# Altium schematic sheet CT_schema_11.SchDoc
size 387 x 278 mm
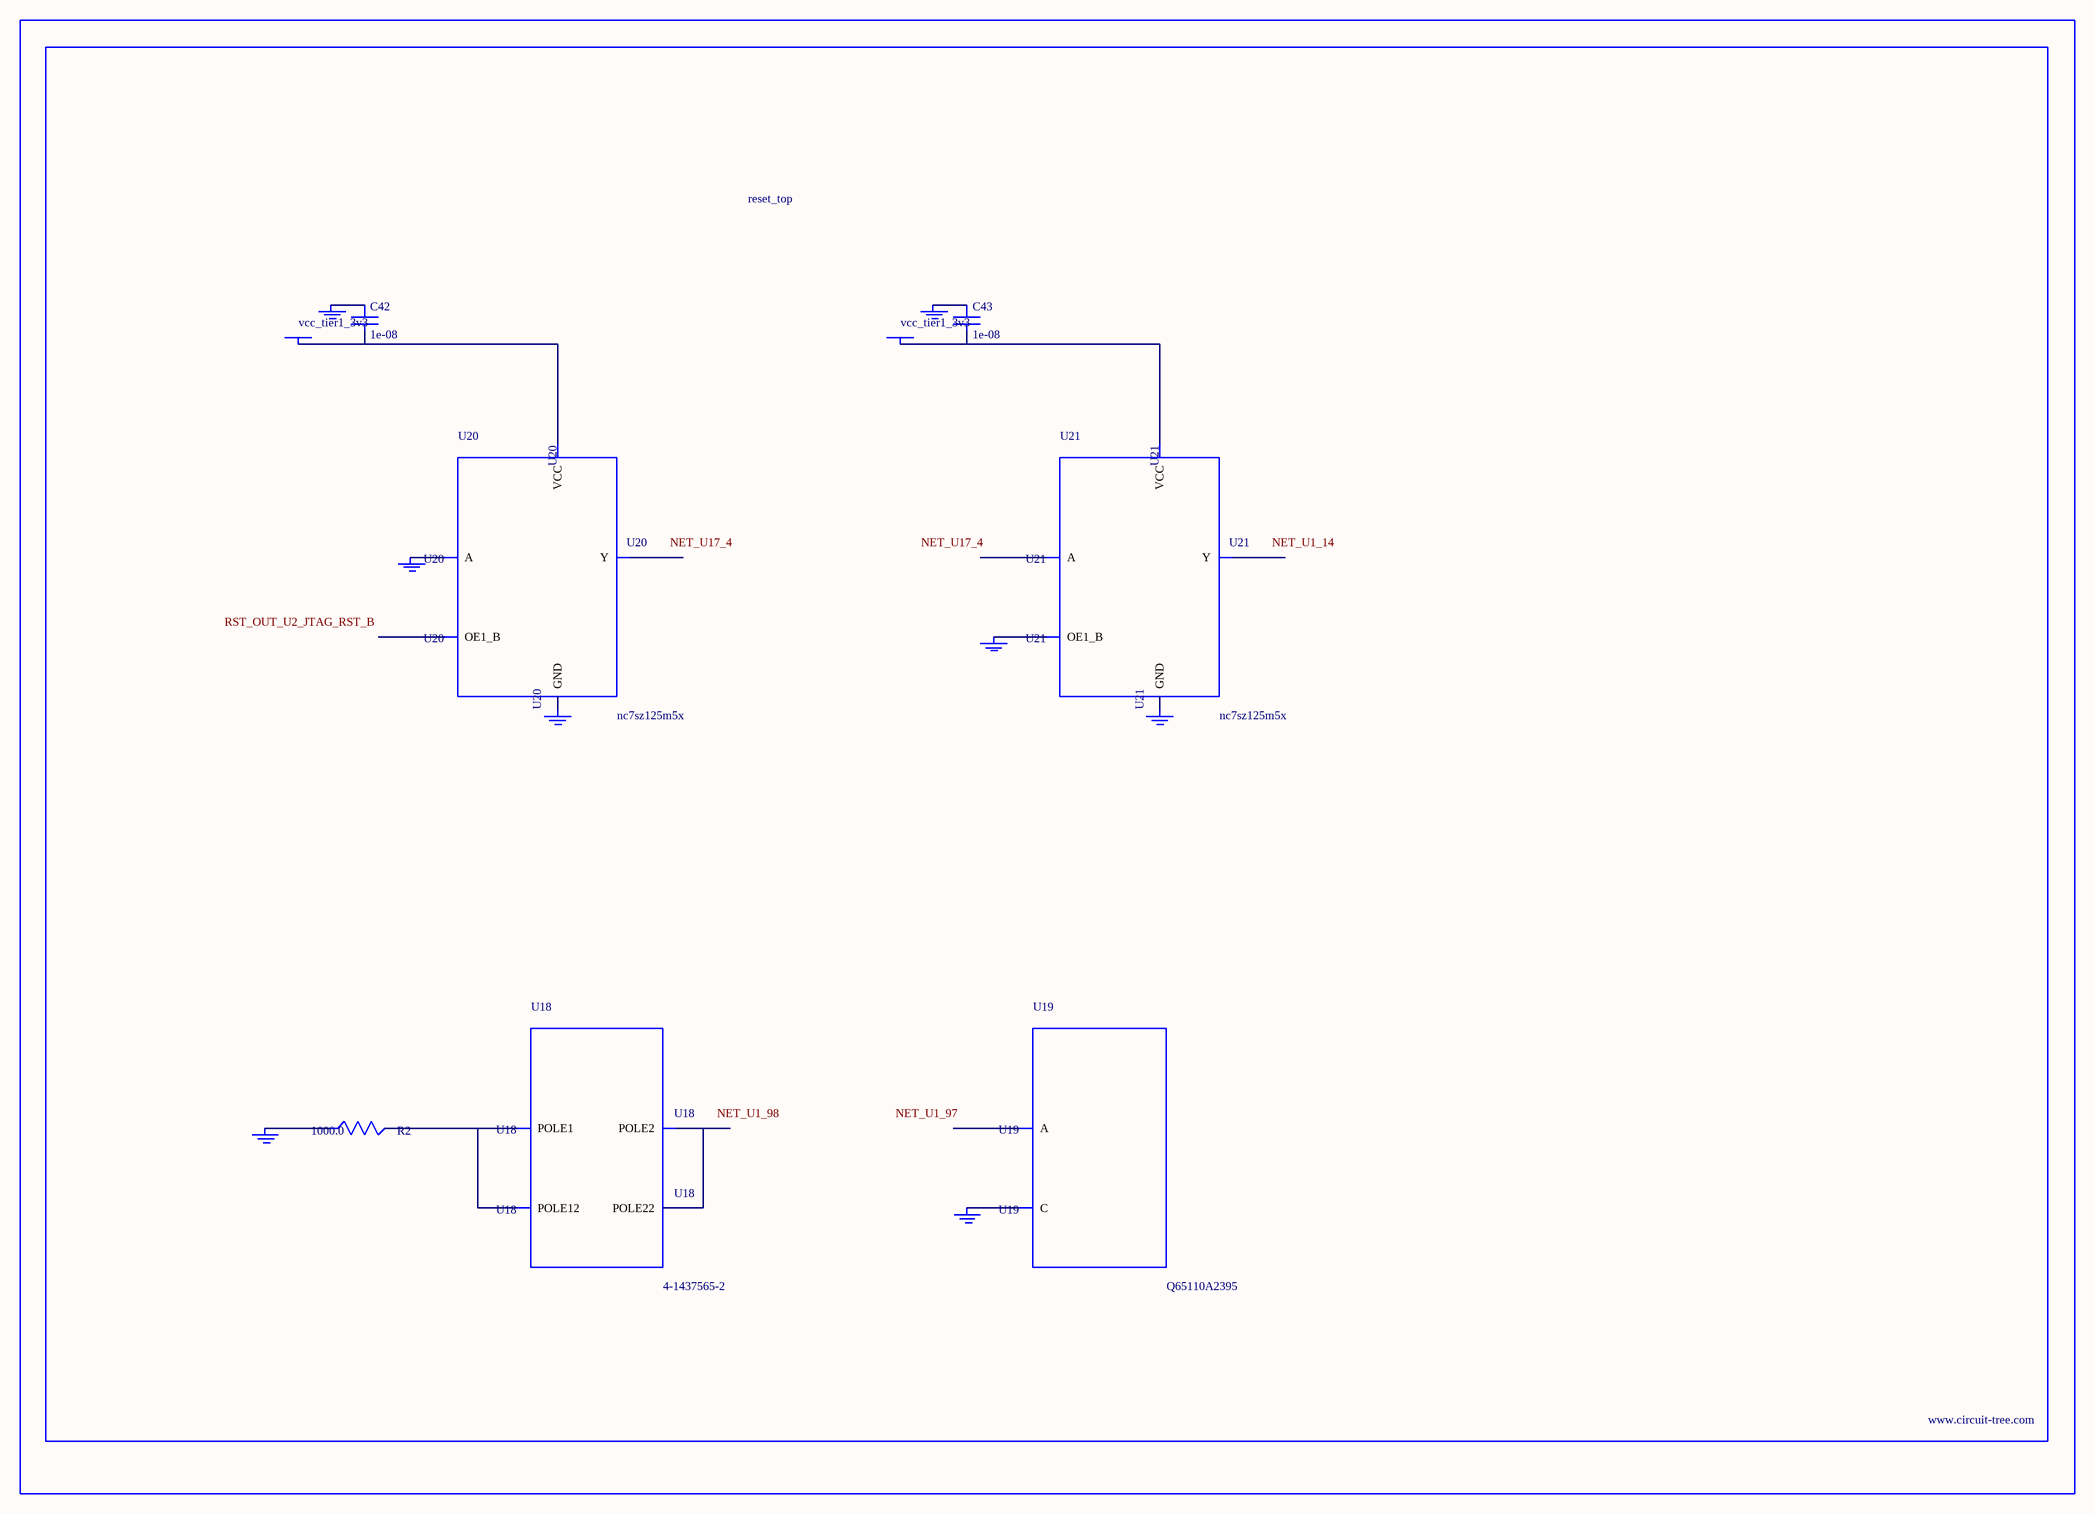
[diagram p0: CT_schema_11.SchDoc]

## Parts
BORDER10  (no value)
C42  1e-08  [C0402]
C43  1e-08  [C0402]
GND_INSTANCE_10_0  (no value)
GND_INSTANCE_10_1  (no value)
GND_INSTANCE_10_2  (no value)
GND_INSTANCE_10_3  (no value)
GND_INSTANCE_10_4  (no value)
GND_INSTANCE_10_5  (no value)
GND_INSTANCE_10_6  (no value)
GND_INSTANCE_10_7  (no value)
POWER_INSTANCE_10_0  vcc_tier1_3v3
POWER_INSTANCE_10_1  vcc_tier1_3v3
R2  1000.0  [R0603]
U18  4-1437565-2  [SW_4-1437565-2]
U19  Q65110A2395  [LGM67K-G1J2-24-Z]
U20  nc7sz125m5x  [NC7SZ125M5X]
U21  nc7sz125m5x  [NC7SZ125M5X]

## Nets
NetC42_1: C42.1 GND_INSTANCE_10_2.0(GND)
NetC42_2: C42.2 POWER_INSTANCE_10_0.0(PWR) U20.5(VCC)
NetC43_1: C43.1 GND_INSTANCE_10_5.0(GND)
NetC43_2: C43.2 POWER_INSTANCE_10_1.0(PWR) U21.5(VCC)
NetGND_INSTANCE_10_0_0: GND_INSTANCE_10_0.0(GND) R2.1
NetGND_INSTANCE_10_1_0: GND_INSTANCE_10_1.0(GND) U19.C
NetGND_INSTANCE_10_3_0: GND_INSTANCE_10_3.0(GND) U20.2(A)
NetGND_INSTANCE_10_4_0: GND_INSTANCE_10_4.0(GND) U20.3(GND)
NetGND_INSTANCE_10_6_0: GND_INSTANCE_10_6.0(GND) U21.1(OE1_B)
NetGND_INSTANCE_10_7_0: GND_INSTANCE_10_7.0(GND) U21.3(GND)
NetR2_2: R2.2 U18.1(POLE1) U18.2(POLE12)
NetU18_3: U18.3(POLE2) U18.4(POLE22)

Not connected (* = marked no-connect by the designer): U19 A; U20 1(OE1_B) 4(Y); U21 2(A) 4(Y)

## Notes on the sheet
- Labels drawn without touching a wire or pin: NET_U1_14, NET_U1_97, NET_U1_98, NET_U17_4, RST_OUT_U2_JTAG_RST_B

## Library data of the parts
BORDER10 = BORDER_PAGE10
C42 C43 = C0402C103K3RAC
GND_INSTANCE_10_0-GND_INSTANCE_10_7 = GND
POWER_INSTANCE_10_0 POWER_INSTANCE_10_1 = PWR
R2 = RC0603JR-071KL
